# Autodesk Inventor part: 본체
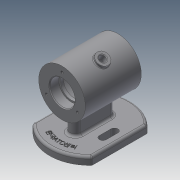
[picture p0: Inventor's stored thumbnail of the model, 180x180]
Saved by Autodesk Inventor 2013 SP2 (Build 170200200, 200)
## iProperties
Created: 2022-02
Part Number: 본체
Material: Generic
Document SubType Name: Modeling
Designer: a
Density: 1 g/cm^3
Author: a
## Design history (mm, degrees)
sketch "스케치1"
  geometry: C1 r 30 at (0, 0); 1 further point
  constraints: 1 centre point, 1 coincident
  dimensions: "d0" = 60 diameter of C1
extrude "돌출1" new body sketch "스케치1" stored distance "d1" = 72; taper "d2" = 0 deg
sketch "스케치2"
  geometry: L1 (30, -36)-(-30, -36) reference; L2 (-30, -36)-(-30, 36) reference; L3 (-30, 36)-(30, 36) reference; L4 (30, 36)-(30, -36) reference; L5 (16, 36)-(16, 24); L6 (16, 24)-(14, 24); L7 (14, 24)-(14, 20); L8 (14, 20)-(25, 20); L9 (25, 20)-(25, -20); L10 (25, -20)-(14, -20); L11 (14, -20)-(14, -24); L12 (14, -24)-(16, -24); L13 (16, -24)-(16, -36); L14 (0, 36)-(0, -36); 1 further point
  constraints: 20 end point, 6 parallel, 3 perpendicular, 2 collinear, 2 midpoint, 2 point on line
  dimensions: "d3" = 32 diameter of L5 L14; "d5" = 28 diameter of L7 L14; "d6" = 40 distance of L8.end L9.end; "d7" = 28 diameter of L11 L14; "d8" = 32 diameter of L13 L14; "d9" = 12 distance of L5.start L5.end; "d10" = 50 diameter of L9 L14
revolve "회전1" sketch "스케치2" stored, may be unused: angle "d11" = 90 deg
fillet "모깎기1" dims "d12" = 3
fillet "모깎기2" dims "d13" = 0.3
chamfer "모따기1" distance "d14" = 1; stored, may be unused: second distance "d15" = 2, angle "d16" = 45 deg
sketch "스케치3"
  geometry: L1 (0, 0)-(0, 23); C1 r 17 at (0, 0) reference; 1 further point
  constraints: 2 end point, 1 coincident, 1 vertical
  dimensions: "d17" = 23 distance of L1.start L1.end
hole "구멍1" sketch "스케치3" at (0, 23) diameter "d18" = 3.242; stored, may be unused: countersink angle "d22" = 82 deg, drill point angle "d24" = 118 deg; dims "d19" = 8, "d20" = 3.023, "d21" = 2, "d23" = 10
node "작업 평면1"
sketch "스케치4"
  geometry: L1 (38, 35.496)-(38, -35.496); L2 (-38, 35.496)-(-38, -35.496); L3 (38, 0)-(-38, 0); A1 r 52 centre (0, 0) between (38, 35.496) and (-38, 35.496); A2 r 52 centre (0, 0) between (-38, -35.496) and (38, -35.496); 2 further points
  constraints: 6 end point, 4 point on circle, 3 midpoint, 2 centre point, 2 coincident, 1 parallel, 1 vertical
  dimensions: "d30" = 76 distance between parallel lines of L2 L1; "d32" = 52 radius of A2
extrude "돌출2" join sketch "스케치4" distance "d33" = 10; taper "d34" = 0 deg
sketch "스케치5"
  geometry: L1 (38, -35.496)-(38, 35.496) reference; L2 (-24, 0)-(24, 0); L3 (-19.5, 12)-(-28.5, 12); L4 (-28.5, 12)-(-28.5, -12); L5 (-28.5, -12)-(-19.5, -12); L6 (-19.5, -12)-(-19.5, 12); L7 (-19.5, 12)-(-28.5, -12); L8 (-28.5, 12)-(-19.5, -12); A1 r 52 centre (0, 0) between (-38, -35.496) and (38, -35.496) reference; 2 further points
  constraints: 14 end point, 4 midpoint, 2 parallel, 2 perpendicular, 1 coincident, 1 horizontal
  dimensions: "d35" = 48 distance of L2.start L2.end; "d66" = 9 distance of L5.end L4.end; "d67" = 24 distance of L4.end L3.end
extrude "돌출3" cut sketch "스케치5" stored distance "d41" = 10; taper "d42" = 0 deg
fillet "모깎기3" dims "d43" = 3
fillet "모깎기4" dims "d44" = 3
sketch "스케치6"
  geometry: L1 (7, 26)-(-7, 26); L2 (-7, 26)-(-7, -26); L3 (-7, -26)-(7, -26); L4 (7, -26)-(7, 26); L5 (7, 26)-(-7, -26); L6 (-7, 26)-(7, -26); A1 r 49 centre (0, 0) between (-35, -34.293) and (35, -34.293) reference
  constraints: 12 end point, 2 midpoint, 2 parallel, 1 horizontal, 1 perpendicular
  dimensions: "d45" = 14 distance of L3.end L2.end; "d46" = 52 distance of L2.end L1.end
extrude "돌출4" join sketch "스케치6" stored distance "d47" = 10; taper "d48" = 0 deg
fillet "모깎기5" dims "d49" = 7
sketch "스케치7"
  geometry: L1 (7, -29.172)-(7, -52) reference; L2 (7, -52)-(35, -52) reference; L3 (-19.5, -52)-(-7, -52) reference; L4 (-7, -52)-(-7, -29.172) reference; L5 (38, -55)-(38, -62) reference; L6 (38, -62)-(-19.5, -62) reference; L7 (-38, -62)-(-38, -55) reference; L8 (0, 0)-(16.5, 28.579); L9 (0, 0)-(0, 30); L10 (-19.5, -62)-(-19.5, -52) reference; L11 (-35, -52)-(-28.5, -52) reference; L12 (-28.5, -52)-(-28.5, -62) reference; L13 (-28.5, -62)-(-38, -62) reference; C1 r 25 at (0, 0) reference; A1 r 30 centre (0, 0) between (7, -29.172) and (-7, -29.172) reference; A2 r 3 centre (35, -55) between (38, -55) and (35, -52) reference; A3 r 3 centre (-35, -55) between (-35, -52) and (-38, -55) reference; 2 further points
  constraints: 4 end point, 1 coincident, 1 point on circle
  dimensions: "d50" = 33 distance of L8.start L8.end; "d52" = 30 deg angle of L8 L9
  node "절단 모서리 투영2"
node "작업 평면2"
sketch "스케치8"
  geometry: C1 r 8 at (0, 0); 1 further point
  constraints: 1 centre point, 1 coincident
  dimensions: "d53" = 16 diameter of C1
extrude "돌출5" join sketch "스케치8" stored distance "d54" = 10; taper "d55" = 0 deg
sketch "스케치9"
  geometry: C1 r 8 at (0, 0) reference; C2 r 4 at (0, 0)
  constraints: 1 centre point, 1 coincident
  dimensions: "d56" = 8 diameter of C2
extrude "돌출6" cut sketch "스케치9" stored distance "d57" = 10; taper "d58" = 0 deg
fillet "모깎기6" dims "d59" = 1
fillet "모깎기7" dims "d60" = 1
fillet "모깎기8" dims "d61" = 3
sketch "스케치10"
  geometry: C1 r 42.5 at (0, 0); A1 r 49 centre (0, 0) between (35, 34.293) and (-35, 34.293) reference
  constraints: 1 centre point, 1 coincident, 1 other
  dimensions: "d62" = 85 diameter of C1
feature "엠보싱1" sketch "스케치10" dims "d2" = 0, "d12" = 3, "d64" = 0.5, "d65" = 0
fillet "모깎기9" dims "d68" = 4.5
node "솔리드1"
pattern_circular "원형 패턴1" dims angle "d26" = 360 deg
mirror "대칭1"
mirror "대칭3"
node "절단 모서리 투영1"
other parameters: "d28" = -62
